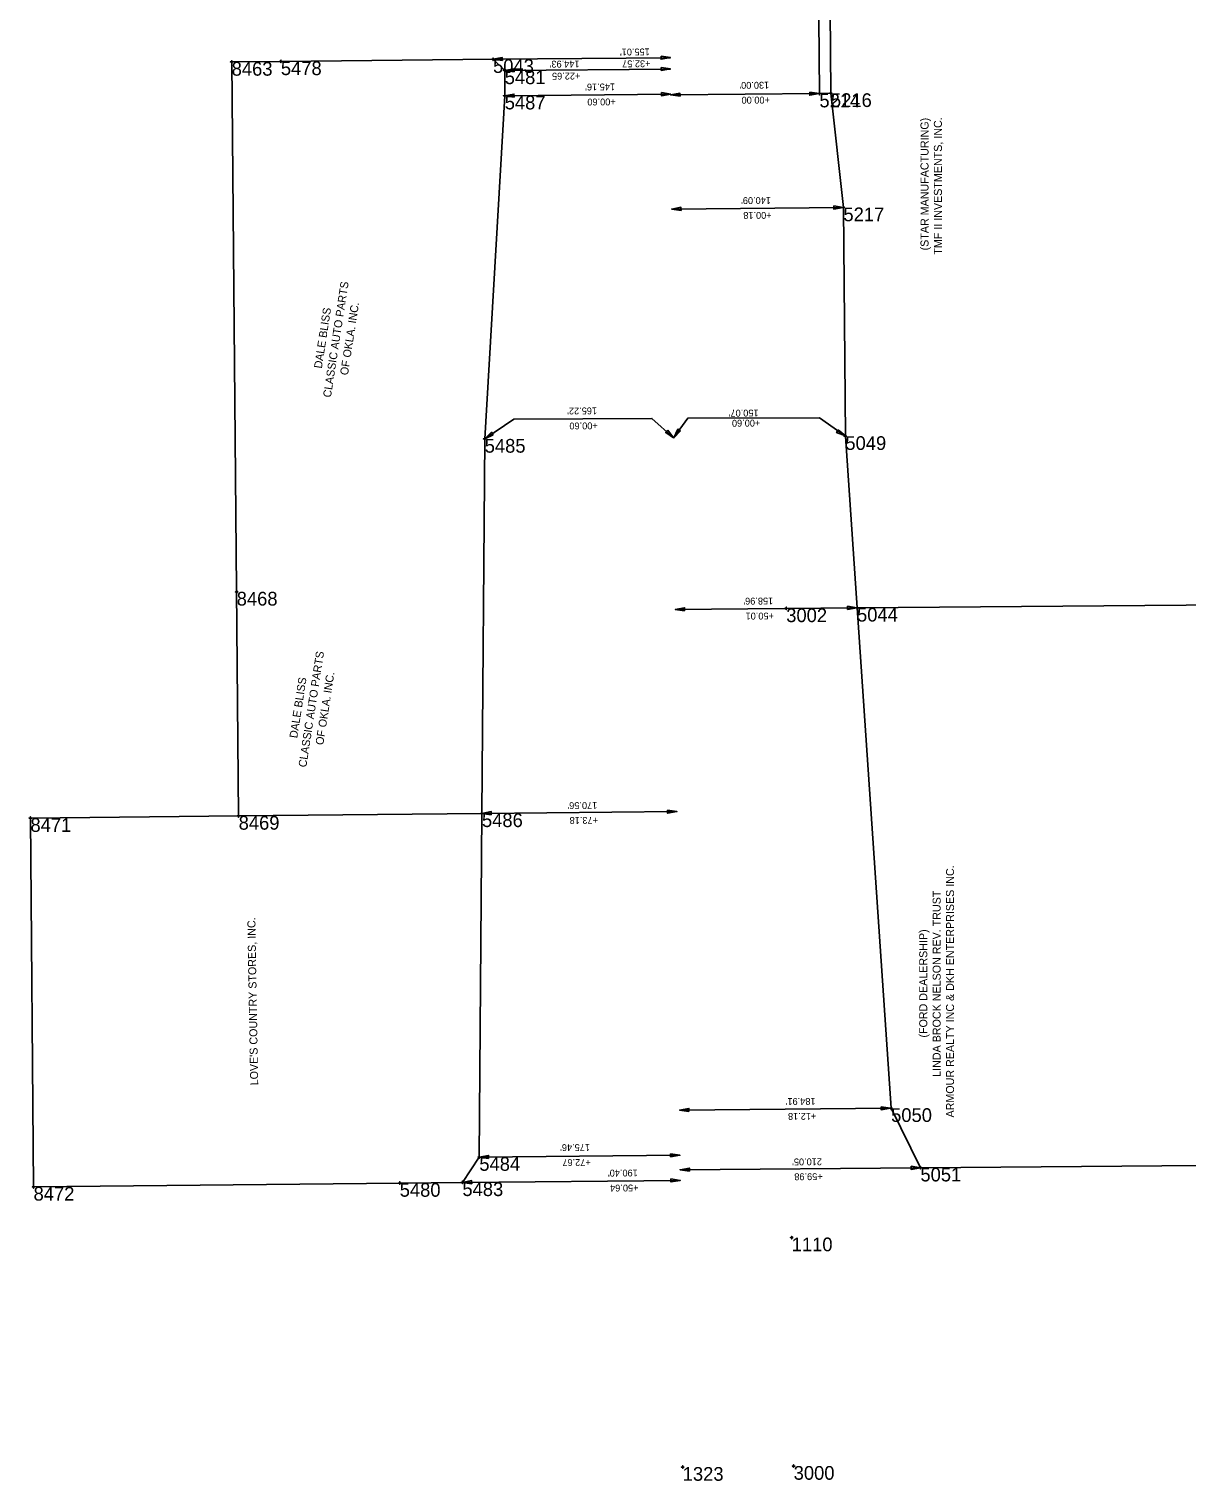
# Model space of a CAD drawing. Extents: x 2145146 to 2158053, y 137507 to 150829.
# Drawn here: x 2150301 to 2151313, y 137507 to 138777 of the extents above; entities that cross this region are included whole.
import ezdxf

# ---------------------------------------------------------------- set-up
doc = ezdxf.new("R2010")
doc.units = 0
for name, color, linetype in [('ALIGN_Cogo Points', 7, 'Continuous'), ('ALIGN_ROW Dimension', 7, 'Continuous'), ('ALIGN_ROW Line', 7, 'Continuous'), ('PLSS_Easement', 7, 'Continuous'), ('PLSS_Property Line', 7, 'Continuous'), ('PLSS_Text_TURNED OFF', 7, 'Continuous')]:
    doc.layers.add(name, color=color, linetype=linetype)

# ---------------------------------------------------------------- blocks, each defined once
blk = doc.blocks.new('Arrowhd')
at = {"layer": 'PLSS_Property Line'}
blk.add_lwpolyline([(0.125, -0.021), (0.125, 0.021), (0, 0)], close=True, dxfattribs=at)

msp = doc.modelspace()

# ---------------------------------------------------------------- linework, layer by layer
at = {"layer": 'ALIGN_Cogo Points'}
for points in [[(2150478.3, 138748.2), (2150478.3, 138749.4), (2150478.3, 138748.2), (2150477.1, 138748.2), (2150478.3, 138748.2), (2150478.3, 138747), (2150478.3, 138748.2), (2150479.5, 138748.2)], [(2150521.3, 138748.7), (2150521.3, 138749.9), (2150521.3, 138748.7), (2150520.1, 138748.7), (2150521.3, 138748.7), (2150521.3, 138747.5), (2150521.3, 138748.7), (2150522.5, 138748.7)], [(2150706.8, 138750.6), (2150706.8, 138751.8), (2150706.8, 138750.6), (2150705.6, 138750.6), (2150706.8, 138750.6), (2150706.8, 138749.4), (2150706.8, 138750.6), (2150708, 138750.6)], [(2150717, 138740.8), (2150717, 138742), (2150717, 138740.8), (2150715.8, 138740.8), (2150717, 138740.8), (2150717, 138739.6), (2150717, 138740.8), (2150718.2, 138740.8)], [(2150717, 138718.7), (2150717, 138719.9), (2150717, 138718.7), (2150715.8, 138718.7), (2150717, 138718.7), (2150717, 138717.5), (2150717, 138718.7), (2150718.2, 138718.7)], [(2150992.1, 138720.5), (2150992.1, 138721.7), (2150992.1, 138720.5), (2150990.9, 138720.5), (2150992.1, 138720.5), (2150992.1, 138719.3), (2150992.1, 138720.5), (2150993.3, 138720.5)], [(2151002.2, 138720.8), (2151002.2, 138722), (2151002.2, 138720.8), (2151001, 138720.8), (2151002.2, 138720.8), (2151002.2, 138719.6), (2151002.2, 138720.8), (2151003.4, 138720.8)], [(2151013.1, 138620.9), (2151013.1, 138622.1), (2151013.1, 138620.9), (2151011.9, 138620.9), (2151013.1, 138620.9), (2151013.1, 138619.7), (2151013.1, 138620.9), (2151014.3, 138620.9)], [(2150699.5, 138418.5), (2150699.5, 138419.7), (2150699.5, 138418.5), (2150698.3, 138418.5), (2150699.5, 138418.5), (2150699.5, 138417.3), (2150699.5, 138418.5), (2150700.7, 138418.5)], [(2151014.8, 138420.9), (2151014.8, 138422.1), (2151014.8, 138420.9), (2151013.6, 138420.9), (2151014.8, 138420.9), (2151014.8, 138419.7), (2151014.8, 138420.9), (2151016, 138420.9)], [(2150482.7, 138284.8), (2150482.7, 138286), (2150482.7, 138284.8), (2150481.5, 138284.8), (2150482.7, 138284.8), (2150482.7, 138283.6), (2150482.7, 138284.8), (2150483.9, 138284.8)], [(2150963.1, 138270.3), (2150963.1, 138271.5), (2150963.1, 138270.3), (2150961.9, 138270.3), (2150963.1, 138270.3), (2150963.1, 138269.1), (2150963.1, 138270.3), (2150964.3, 138270.3)], [(2151025, 138270.8), (2151025, 138272), (2151025, 138270.8), (2151023.8, 138270.8), (2151025, 138270.8), (2151025, 138269.6), (2151025, 138270.8), (2151026.2, 138270.8)], [(2150302.4, 138086.9), (2150302.4, 138088.1), (2150302.4, 138086.9), (2150301.2, 138086.9), (2150302.4, 138086.9), (2150302.4, 138085.7), (2150302.4, 138086.9), (2150303.6, 138086.9)], [(2150484.4, 138088.8), (2150484.4, 138090), (2150484.4, 138088.8), (2150483.2, 138088.8), (2150484.4, 138088.8), (2150484.4, 138087.6), (2150484.4, 138088.8), (2150485.6, 138088.8)], [(2150697.1, 138091.1), (2150697.1, 138092.3), (2150697.1, 138091.1), (2150695.9, 138091.1), (2150697.1, 138091.1), (2150697.1, 138089.9), (2150697.1, 138091.1), (2150698.3, 138091.1)], [(2151054.8, 137833.2), (2151054.8, 137834.4), (2151054.8, 137833.2), (2151053.6, 137833.2), (2151054.8, 137833.2), (2151054.8, 137832), (2151054.8, 137833.2), (2151056, 137833.2)], [(2150694.8, 137790.5), (2150694.8, 137791.7), (2150694.8, 137790.5), (2150693.6, 137790.5), (2150694.8, 137790.5), (2150694.8, 137789.3), (2150694.8, 137790.5), (2150696, 137790.5)], [(2151080.4, 137781.2), (2151080.4, 137782.4), (2151080.4, 137781.2), (2151079.2, 137781.2), (2151080.4, 137781.2), (2151080.4, 137780), (2151080.4, 137781.2), (2151081.6, 137781.2)], [(2150625.2, 137767.8), (2150625.2, 137769), (2150625.2, 137767.8), (2150624, 137767.8), (2150625.2, 137767.8), (2150625.2, 137766.6), (2150625.2, 137767.8), (2150626.4, 137767.8)], [(2150680, 137768.4), (2150680, 137769.6), (2150680, 137768.4), (2150678.8, 137768.4), (2150680, 137768.4), (2150680, 137767.2), (2150680, 137768.4), (2150681.2, 137768.4)], [(2150305.1, 137764.4), (2150305.1, 137765.6), (2150305.1, 137764.4), (2150303.9, 137764.4), (2150305.1, 137764.4), (2150305.1, 137763.2), (2150305.1, 137764.4), (2150306.3, 137764.4)], [(2150967.9, 137720.1), (2150967.9, 137721.3), (2150967.9, 137720.1), (2150966.7, 137720.1), (2150967.9, 137720.1), (2150967.9, 137718.9), (2150967.9, 137720.1), (2150969.1, 137720.1)], [(2150872.6, 137519.4), (2150872.6, 137520.6), (2150872.6, 137519.4), (2150871.4, 137519.4), (2150872.6, 137519.4), (2150872.6, 137518.2), (2150872.6, 137519.4), (2150873.8, 137519.4)], [(2150969.6, 137520.3), (2150969.6, 137521.5), (2150969.6, 137520.3), (2150968.4, 137520.3), (2150969.6, 137520.3), (2150969.6, 137519.1), (2150969.6, 137520.3), (2150970.8, 137520.3)]]:
    msp.add_lwpolyline(points, dxfattribs=at)
at = {"layer": 'ALIGN_ROW Dimension'}
for points in [[(2150706.8, 138750.6), (2150861.8, 138751.9)], [(2150717, 138740.8), (2150861.9, 138742)], [(2150717, 138718.7), (2150862.1, 138720)], [(2150992.1, 138720.5), (2150862.1, 138719.4)], [(2151013.1, 138620.9), (2150863, 138619.6)], [(2150864.7, 138419.6), (2150845.7, 138436.5), (2150724.9, 138435.9), (2150699.5, 138418.5)], [(2150864.7, 138419.6), (2150877, 138436.6), (2150992.3, 138436.9), (2151014.8, 138420.9)], [(2151025, 138270.8), (2150866.1, 138269.4)], [(2150697.1, 138091.1), (2150867.6, 138092.6)], [(2151054.6, 137833.2), (2150869.9, 137831.6)], [(2150694.8, 137790.5), (2150870.2, 137792.1)], [(2151080.4, 137781.2), (2150870.3, 137779.4)], [(2150680, 137768.4), (2150870.4, 137770.1)]]:
    msp.add_lwpolyline(points, dxfattribs=at)
at = {"layer": 'ALIGN_ROW Line'}
for points in [[(2151467.6, 137757.4), (2151467.4, 137784.4), (2151080.4, 137781.2), (2151054.8, 137833.2), (2151025, 138270.8), (2151014.8, 138420.9), (2151013.1, 138620.9), (2151002.2, 138720.8), (2150992.1, 138720.5), (2150984.4, 139606.7), (2150993.3, 139722.5), (2151034.1, 140247.7), (2151053, 140291.9), (2151058.3, 140359.7), (2151125.2, 141214)], [(2150521.3, 138748.7), (2150706.8, 138750.6), (2150717, 138740.8), (2150717, 138718.7), (2150699.5, 138418.5), (2150697.1, 138091.1), (2150694.8, 137790.5), (2150680, 137768.4), (2150625.2, 137767.8)]]:
    msp.add_lwpolyline(points, dxfattribs=at)
at = {"layer": 'PLSS_Easement'}
msp.add_lwpolyline([(2151002.2, 138720.8), (2150995, 139590.2)], dxfattribs=at)
at = {"layer": 'PLSS_Property Line'}
for points in [[(2150697, 138091.1), (2150484.4, 138088.8), (2150478.3, 138748.2), (2150521.3, 138748.7)], [(2152283.1, 138281.1), (2151025, 138270.8)], [(2150484.4, 138088.8), (2150302.4, 138086.9), (2150305.1, 137764.4), (2150625.2, 137767.8)]]:
    msp.add_lwpolyline(points, dxfattribs=at)

# ---------------------------------------------------------------- block references
at = {"layer": 'ALIGN_ROW Dimension'}
for p, xscale, yscale, rotation in [((2150706.8, 138750.6), 65.00000000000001, 65, 0.7805293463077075), ((2150861.8, 138752), 65, 65, 180), ((2150717, 138740.8), 65.00000000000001, 65, 0.7805293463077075), ((2150861.9, 138742.1), 65, 65, 180), ((2150717, 138718.7), 65.00000000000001, 65, 0.7805293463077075), ((2150862.1, 138720), 65, 65, 180), ((2150862.1, 138719.4), 65.00000000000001, 65, 0.7805293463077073), ((2150991.8, 138720.5), 65, 65, 180), ((2150863, 138619.6), 65.00000000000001, 65, 0.7805293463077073), ((2151012.8, 138620.9), 65, 65, 180), ((2150864.8, 138419.6), 65.00000000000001, 65.00000000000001, 55.03308120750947), ((2150699.6, 138418.6), 65.00000000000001, 65, 35.18012583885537), ((2150864.7, 138419.6), 65, 65, 137.76118620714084), ((2151014.8, 138421.1), 65, 65, 149.00250710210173), ((2150866.1, 138269.4), 65.00000000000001, 65, 0.7805293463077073), ((2151024.8, 138270.8), 65, 65, 180), ((2150697.1, 138091.1), 65.00000000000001, 65, 0.7805293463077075), ((2150867.5, 138092.6), 65, 65, 180), ((2150869.9, 137831.6), 65.00000000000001, 65, 0.7805293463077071), ((2151054.2, 137833.2), 65, 65, 180), ((2150694.8, 137790.5), 65.00000000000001, 65, 0.7805293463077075), ((2150870.2, 137792.1), 65, 65, 180), ((2150870.3, 137779.4), 65.00000000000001, 65, 0.7805293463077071), ((2151080.4, 137781.2), 65, 65, -179.2781478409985), ((2150680, 137768.4), 65.00000000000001, 65, 0.7805293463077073), ((2150870.4, 137770.1), 65, 65, 180)]:
    msp.add_blockref('Arrowhd', p, dxfattribs=dict(at, xscale=xscale, yscale=yscale, rotation=rotation))

# ---------------------------------------------------------------- texts
at = {"layer": 'ALIGN_Cogo Points'}
for s, p in [('8463', (2150478.3, 138736.2)), ('5478', (2150521.3, 138736.7)), ('5043', (2150706.8, 138738.6)), ('5481', (2150717, 138728.8)), ('5487', (2150717, 138706.7)), ('5214', (2150992.1, 138708.5)), ('5216', (2151002.2, 138708.8)), ('5217', (2151013.1, 138608.9)), ('5485', (2150699.5, 138406.5)), ('5049', (2151014.8, 138408.9)), ('8468', (2150482.7, 138272.8)), ('3002', (2150963.1, 138258.3)), ('5044', (2151025, 138258.8)), ('8471', (2150302.4, 138074.9)), ('8469', (2150484.4, 138076.8)), ('5486', (2150697.1, 138079.1)), ('5050', (2151054.8, 137821.2)), ('5484', (2150694.8, 137778.5)), ('5051', (2151080.4, 137769.2)), ('5480', (2150625.2, 137755.8)), ('5483', (2150680, 137756.4)), ('8472', (2150305.1, 137752.4)), ('1110', (2150967.9, 137708.1)), ('1323', (2150872.6, 137507.4)), ('3000', (2150969.6, 137508.3))]:
    msp.add_text(s, height=12, dxfattribs=at).set_placement(p)
at = {"layer": 'ALIGN_ROW Dimension'}
for s, p in [("155.01'", (2150843.8, 138760)), ("144.93'", (2150782.4, 138749.4)), ('+32.57', (2150844.4, 138749.7)), ('+22.65', (2150783.1, 138738.9)), ("145.16'", (2150813.4, 138729.4)), ("130.00'", (2150948.2, 138730.9)), ('+00.60', (2150814, 138716.3)), ('+00.00', (2150948.8, 138717.9)), ("140.09'", (2150949.7, 138630.1)), ('+00.18', (2150950.3, 138617.1)), ("165.22'", (2150797.7, 138446.1)), ("150.07'", (2150938.9, 138444.2)), ('+00.60', (2150798.3, 138433)), ('+00.60', (2150940.4, 138435.4)), ("158.96'", (2150951.7, 138279.8)), ('+50.01', (2150952.3, 138266.7)), ("170.56'", (2150797.9, 138101)), ('+73.18', (2150798.5, 138088)), ("184.91'", (2150988.7, 137842.2)), ('+12.18', (2150989.4, 137829.2)), ("175.46'", (2150791.5, 137801.9)), ('+72.67', (2150792.2, 137788.8)), ("190.40'", (2150833.3, 137779.6)), ("210.05'", (2150994.3, 137789.4)), ('+50.64', (2150833.9, 137766.5)), ('+59.98', (2150994.9, 137776.4))]:
    msp.add_text(s, height=6, rotation=180.3718, dxfattribs=at).set_placement(p)
at = {"layer": 'PLSS_Text_TURNED OFF'}
for s, rotation, p in [('(STAR MANUFACTURING)', 90, (2151087.5, 138583.4)), ('TMF II INVESTMENTS, INC.', 90, (2151099.2, 138579.7)), ('CLASSIC AUTO PARTS', 81.2205, (2150565, 138454.4)), ('DALE BLISS', 81.2205, (2150557.1, 138479.8)), ('OF OKLA. INC.', 81.2205, (2150579.9, 138473.9)), ('CLASSIC AUTO PARTS', 81.2205, (2150543.5, 138131)), ('OF OKLA. INC.', 81.2205, (2150558.4, 138150.5)), ('DALE BLISS', 81.2205, (2150535.6, 138156.5)), ('ARMOUR REALTY INC & DKH ENTERPRISES INC.', 90, (2151109.8, 137825.1)), ('LINDA BROCK NELSON REV. TRUST', 90, (2151098.1, 137860.7)), ("LOVE'S COUNTRY STORES, INC.", 90.9865, (2150501.5, 137853.3)), ('(FORD DEALERSHIP)', 90, (2151086.4, 137895))]:
    msp.add_text(s, height=7, rotation=rotation, dxfattribs=at).set_placement(p)

doc.saveas('drawing.dxf')
